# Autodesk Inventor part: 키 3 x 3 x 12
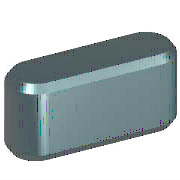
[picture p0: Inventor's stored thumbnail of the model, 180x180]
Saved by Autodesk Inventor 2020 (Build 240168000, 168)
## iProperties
Created: 2012-02
Part Number: 키 3 x 3 x 12
Material: 강철, 연강
Description: 키 및 해당 키홈
Document SubType Name: Modeling
Standard: KS B 1311
Designer: mduedu
Standards Organization: KS
Language: ko-KR
Size Designation: 3 x 3 x 12
Categories: <MemberInstance><Categories><Category DisplayName="샤프트 부품" InternalName="7f7aeb1f-a693-4053-b835-cee3144e0d98" Mnemonic="SHFT"><Category DisplayName="키" Interna
Density: 1 g/cm^3
Appearance: 노란색
IsCustomPart: 1
Author: mduedu
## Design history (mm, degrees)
workplane "Work Plane1"
workplane "Work Plane2"
sketch "스케치1"
  geometry: L1 (1.5, 1.5)-(10.5, 1.5); L2 (10.5, -1.5)-(1.5, -1.5); L3 (0, 9.4)-(0, -7.4) reference; L4 (-5, 0)-(30, 0) reference; L5 (12, 0)-(12, 7); A1 r 1.5 centre (1.5, 0) between (1.5, 1.5) and (1.5, -1.5); A2 r 1.5 centre (10.5, 0) between (10.5, -1.5) and (10.5, 1.5)
  constraints: 6 end point, 5 point on circle, 4 tangent, 3 point on line, 2 centre point, 1 horizontal, 1 parallel, 1 perpendicular
  dimensions: "d0" = 1.5 radius of A1 (= 0.5 x PB); "d13" = 1.5 radius of A2 (= 0.5 x PB); "d14" = 12 distance between parallel lines of L5 L3 (= NLG)
extrude "본체1" new body sketch "스케치1" taper "d3" = 0 deg; stored distance "d4" = 10
workplane "Work Plane3"
body "Solid1"
chamfer "모따기1" distance "d8" = 0.25 (= PHH); stored, may be unused: second distance "d9" = 0.25 (= PHH), angle "d15" = 45 deg
other parameters: "d1" = -1.8 (= -PNT), "d2" = 1.2 (= PH - PNT), "NLG" = 12 [user parameter; used in 3 equation terms], "PB" = 3 [user parameter; used in 2 equation terms], "PNT" = 1.8 [user parameter; used in 2 equation terms], "PH" = 3 [user parameter; used in 1 equation term], "PHH" = 0.25 [user parameter; used in 2 equation terms], "d10" = 0, "d16" = 0, "d17" = 0, "d18" = 0, "WDMIN" = 8 [user parameter], "PLB2" = 12 (= NLG) [user parameter], "PLB1" = 12 (= NLG) [user parameter], "RR" = 0.08 [user parameter], "PUEB" = 1.4 [user parameter]
